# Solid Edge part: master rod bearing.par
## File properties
Author: Vicky Raina
Template: Normal.par
Last saved by: Robert a Rhodes jr
Revision: 2
Application: Solid Edge
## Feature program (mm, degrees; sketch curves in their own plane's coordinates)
sketch for "unnamed Protrusion 1" #1 plane through (0, 0, 0) normal (0, 0, 1) x-axis (1, 0, 0)
  circle centre (0, 0) radius 23
sketch for "unnamed Protrusion 1" #2 plane through (0, 0, 0) normal (0, 0, 1) x-axis (1, 0, 0)
  circle centre (0, 0) radius 26
extrude "unnamed Protrusion 1" add finite 70 along -normal
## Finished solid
Body 1: solid body, 4 faces, 4 edges, 0 vertices.
  Faces by surface: cylinder 2, plane 2
  Edges by curve: circle 4
Bounding box of the edges (mm): 52.000 x 52.000 x 70.000, from (-26, -26, -70) to (26, 26, 0).
Cylindrical faces by radius (mm): R23 x1, R26 x1
Planar faces by outward normal: +z 1, -z 1
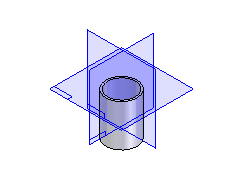
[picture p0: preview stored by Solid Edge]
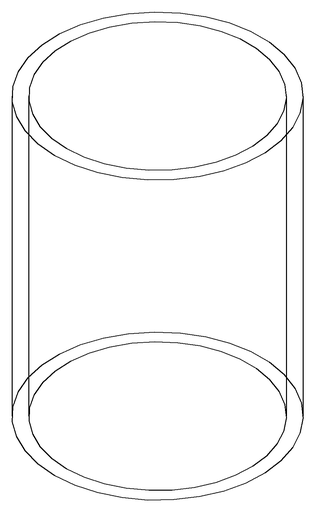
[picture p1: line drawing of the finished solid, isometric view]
